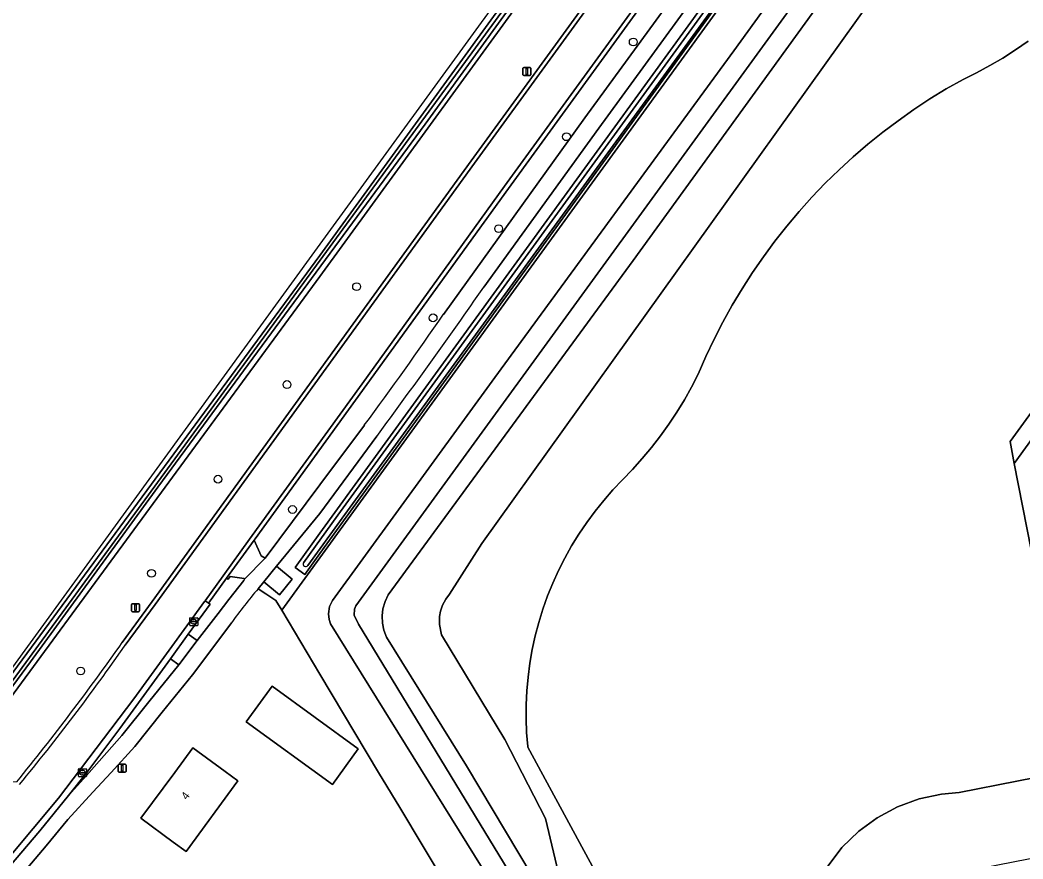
# Model space of a CAD drawing. Extents: x 152881 to 155736, y 382924 to 386919.
# Drawn here: x 152962.5 to 153087.9, y 384989.2 to 385094 of the extents above; entities that cross this region are included whole.
import ezdxf

# ---------------------------------------------------------------- set-up
doc = ezdxf.new("R2010")
doc.units = 0
for name, color, linetype in [('IMGEO_Berm_groen', 7, 'Continuous'), ('IMGEO_Boom', 7, 'Continuous'), ('IMGEO_Erf', 7, 'Continuous'), ('IMGEO_Fietspad_gesloten', 7, 'Continuous'), ('IMGEO_Groenvoorziening', 7, 'Continuous'), ('IMGEO_Kolk', 7, 'Continuous'), ('IMGEO_Lichtmast', 7, 'Continuous'), ('IMGEO_Loofbos', 7, 'Continuous'), ('IMGEO_Oever', 7, 'Continuous'), ('IMGEO_Pand', 7, 'Continuous'), ('IMGEO_Pand_nummerreeks', 7, 'Continuous'), ('IMGEO_Rijbaan_lokaal_gesloten', 7, 'Continuous'), ('IMGEO_Rijbaan_lokaal_open', 7, 'Continuous'), ('IMGEO_Verkeersbordpaal', 7, 'Continuous'), ('IMGEO_Waterloop', 7, 'Continuous')]:
    doc.layers.add(name, color=color, linetype=linetype)

msp = doc.modelspace()

# ---------------------------------------------------------------- linework, layer by layer
at = {"layer": 'IMGEO_Berm_groen'}
for points in [[(153073.4, 385137.04), (153085.12, 385153.13), (153082.24, 385153.77), (153023.56, 385073.01), (153005.89, 385048.49), (152991.9, 385029.19), (152991.77, 385029.01), (152992.68, 385027.08), (152993.15, 385026.8), (153000, 385035.96), (153005.56, 385043.4)], [(153015.45, 385057.26), (153033.13, 385081.82), (153073.4, 385137.04)]]:
    msp.add_lwpolyline(points, dxfattribs=at)
for points in [[(152988.61, 385021.62), (152990.48, 385023.99), (152990.6, 385024.15), (152990.52, 385024.24), (152988.78, 385024.48), (152988.54, 385024.15), (152988.34, 385024.29), (152986.07, 385021.17), (152986.27, 385021.02), (152983.55, 385017.27), (152984.67, 385016.47), (152987.3, 385019.88)], [(152982.36, 385013.46), (152981.33, 385014.2), (152975.01, 385005.47), (152970.89, 385000), (152968.6, 384997.09), (152971.18, 385000), (152975.26, 385004.6), (152978.61, 385008.8)]]:
    msp.add_lwpolyline(points, close=True, dxfattribs=at)
msp.add_arc((152623.6, 385326.44), 475.4, 323.4603, 325.5136, dxfattribs=at)
at = {"layer": 'IMGEO_Boom'}
for centre in [(153039.17, 385091.31), (153030.82, 385079.46), (153022.35, 385067.97), (153004.59, 385060.72), (153014.15, 385056.82), (152995.89, 385048.48), (152987.27, 385036.65), (152996.58, 385032.87), (152978.95, 385024.88), (152970.11, 385012.68)]:
    msp.add_circle(centre, 0.489, dxfattribs=at)
at = {"layer": 'IMGEO_Erf'}
for points in [[(153009.98, 384995.61), (153007.35, 385000), (153000, 385012.28), (152995.23, 385020.26), (152995.25, 385020.29), (152994.51, 385021.5), (152993.25, 385022.33), (152992.29, 385022.96)], [(152988.96, 385018.7), (152986.37, 385015.25), (152984.09, 385012.21), (152980.28, 385007.53), (152976.88, 385003.22), (152973.91, 385000), (152971.61, 384997.51), (152968.5, 384994.1), (152965.8, 384990.83), (152962.58, 384987.03)], [(153037.11, 384950.27), (153009.98, 384995.61)]]:
    msp.add_lwpolyline(points, dxfattribs=at)
for points in [[(152990.81, 385006.33), (152994.03, 385010.76), (153004.8, 385002.94), (153001.58, 384998.5)], [(152977.64, 384994.26), (152981.87, 385000), (152984.14, 385003.07), (152988.16, 385000.1), (152989.76, 384998.93), (152983.27, 384990.1), (152981.66, 384991.29)]]:
    msp.add_lwpolyline(points, close=True, dxfattribs=at)
msp.add_arc((153032.46, 384988.09), 53.19, 139.0459, 144.8753, dxfattribs=at)
at = {"layer": 'IMGEO_Fietspad_gesloten'}
for points in [[(153020.5, 385060.66), (153034.86, 385080.54), (153075.16, 385135.82), (153086.86, 385151.87), (153088.71, 385154.45), (153096.42, 385165.12), (153155.57, 385246.33), (153158.23, 385250), (153197.22, 385303.84), (153198.61, 385306.61), (153200.7, 385310.11), (153201.21, 385310.92), (153201.8, 385311.84), (153204.8, 385316.21), (153206.99, 385318.53)], [(153153.91, 385247.68), (153111.75, 385189.75), (153110.83, 385188.49), (153094.69, 385166.3), (153086.99, 385155.68), (153085.12, 385153.13), (153073.4, 385137.04), (153033.13, 385081.82), (153015.45, 385057.26)], [(153005.56, 385043.4), (153000, 385035.96), (152993.15, 385026.8), (152990.6, 385024.15), (152990.48, 385023.99), (152988.61, 385021.62), (152987.3, 385019.88), (152984.67, 385016.47), (152982.36, 385013.46), (152978.61, 385008.8), (152975.26, 385004.6), (152971.18, 385000), (152968.6, 384997.09), (152964.98, 384992.7), (152961.21, 384988.25)], [(152992.29, 385022.96), (152992.99, 385023.81), (152994.59, 385025.76), (153000, 385032.37), (153007.12, 385042.01)], [(152965.8, 384990.83), (152968.5, 384994.1), (152971.61, 384997.51), (152973.91, 385000), (152976.88, 385003.22), (152980.28, 385007.53), (152984.09, 385012.21), (152986.37, 385015.25), (152988.96, 385018.7)], [(152962.58, 384987.03), (152965.8, 384990.83)]]:
    msp.add_lwpolyline(points, dxfattribs=at)
for centre, radius, start, end in [((152288.91, 385571.47), 892.27, 323.60229, 325.0763), ((152623.6, 385326.44), 475.4, 323.4603, 325.5136), ((153032.46, 384988.09), 53.19, 139.0459, 144.8753)]:
    msp.add_arc(centre, radius, start, end, dxfattribs=at)
at = {"layer": 'IMGEO_Groenvoorziening'}
for points in [[(153162.04, 385250), (153199.79, 385301.98), (153198.73, 385302.74), (153197.22, 385303.84), (153158.23, 385250), (153155.57, 385246.33), (153096.42, 385165.12), (153088.71, 385154.45), (153090.14, 385153.44), (153088.3, 385150.85), (153086.86, 385151.87), (153075.16, 385135.82), (153034.86, 385080.54), (153020.5, 385060.66)], [(153007.12, 385042.01), (153000, 385032.37), (152994.59, 385025.76), (152996.55, 385024.15), (152994.96, 385022.2), (152992.99, 385023.81), (152992.29, 385022.96), (152993.25, 385022.33), (152994.51, 385021.5), (152995.25, 385020.29), (153162.04, 385250)], [(153162.04, 385250), (152995.25, 385020.29), (152995.23, 385020.26), (153000, 385012.28), (153007.35, 385000), (153009.98, 384995.61), (153037.11, 384950.27)], [(153164.79, 385228.23), (153133.84, 385185.19), (153103.74, 385143.75), (153071.3, 385099.91), (153020.24, 385028.62), (153016.19, 385022.27), (153015.73, 385021.65), (153015.34, 385020.91), (153015.09, 385020.17), (153014.96, 385019.47), (153014.94, 385018.47), (153015.21, 385017.19), (153023.11, 385004.09), (153028.21, 384994.23), (153029.99, 384986.7)], [(153218.46, 385220.12), (153195.63, 385188.65), (153170.9, 385154.56), (153144.44, 385118.1), (153119.93, 385084.35), (153098.77, 385055.18), (153086.8, 385038.63), (153094.33, 385000.3), (153096.23, 384990.65), (153073.02, 384986.11)], [(153028.71, 384974.52), (153001.35, 385018.59), (153001.17, 385019.1), (153001.07, 385019.8), (153001.2, 385020.72), (153001.57, 385021.49), (153021.87, 385049.38), (153051.75, 385090.2), (153143.44, 385216.88)], [(153094.35, 385195.81), (153085.56, 385183.72), (153076.06, 385170.64), (153077.51, 385169.6), (153076.65, 385168.36), (153075.17, 385169.42), (153058.94, 385147.09), (153000, 385066.03)], [(152975.29, 385016.24), (152979.03, 385021.37), (153018.92, 385076.46), (153077.76, 385157.41), (153076.54, 385160.34), (153071.56, 385163.75), (153073.52, 385166.38), (153078.5, 385162.91), (153081.57, 385162.66), (153094.38, 385180.27)], [(153169.09, 385155.23), (153086.26, 385041.38), (153086.8, 385038.63), (153098.77, 385055.18)], [(153094.33, 385000.3), (153079.92, 384997.47), (153077.69, 384997.29), (153074.89, 384996.68), (153072.2, 384995.68), (153069.67, 384994.33), (153067.35, 384992.64), (153065.25, 384990.62), (153046.46, 384965.39), (153025.99, 385003.14), (153025.98, 385003.23), (153025.84, 385004.97), (153025.77, 385006.71), (153025.78, 385008.45), (153025.87, 385010.18), (153026.02, 385011.92), (153026.25, 385013.65), (153026.55, 385015.36), (153026.92, 385017.06), (153027.36, 385018.74), (153027.88, 385020.41), (153028.46, 385022.05), (153029.11, 385023.66), (153029.83, 385025.25), (153030.62, 385026.8), (153031.47, 385028.32), (153032.38, 385029.8), (153033.36, 385031.25), (153034.39, 385032.65), (153035.49, 385034), (153036.63, 385035.31), (153037.84, 385036.57), (153039.09, 385037.88), (153040.3, 385039.23), (153041.46, 385040.62), (153042.57, 385042.06), (153043.62, 385043.53), (153044.62, 385045.04), (153045.57, 385046.59), (153046.45, 385048.17), (153047.28, 385049.78), (153048.24, 385051.99), (153049.27, 385054.16), (153050.37, 385056.3), (153051.54, 385058.4), (153052.77, 385060.46), (153054.07, 385062.48), (153055.43, 385064.46), (153056.86, 385066.4), (153058.35, 385068.29), (153059.9, 385070.12), (153061.5, 385071.91), (153063.17, 385073.65), (153064.89, 385075.33), (153066.66, 385076.95), (153068.48, 385078.52), (153070.35, 385080.03), (153072.27, 385081.47), (153074.24, 385082.86), (153076.25, 385084.18), (153078.3, 385085.43), (153080.39, 385086.62), (153082.08, 385087.45), (153083.74, 385088.35), (153085.37, 385089.3), (153086.96, 385090.32), (153088.51, 385091.4)], [(153000, 385066.03), (152987.38, 385048.67), (152957, 385006.89), (152951.3, 385000), (152949.25, 384997.53), (152949.06, 384997.32), (152948.98, 384997.23), (152949.2, 384997.13), (152949.77, 384996.78), (152956.01, 384992.15), (152956.27, 384991.93), (152958.08, 384994.05), (152957.16, 384996.76), (152953.13, 385000), (152952.82, 385000.25), (152952.4, 385000.59), (152954.33, 385002.81), (152954.72, 385002.49), (152957.78, 385000), (152959, 384999), (152962.1, 384998.82)]]:
    msp.add_lwpolyline(points, dxfattribs=at)
for points in [[(153000, 385062), (152957.36, 385003.99), (152956.59, 385004.68), (152956.14, 385005.09), (153000, 385064.61), (153059.58, 385146.65), (153070.73, 385162), (153072.14, 385161.17), (153060.9, 385145.72)], [(153076.27, 385135.05), (153086.45, 385149.09), (153087.17, 385148.56), (153087.55, 385148.28), (153077.4, 385134.26), (153000, 385027.35), (152998.11, 385024.74), (152996.9, 385025.62), (153000, 385029.9)]]:
    msp.add_lwpolyline(points, close=True, dxfattribs=at)
for centre, radius, start, end in [((152288.91, 385571.47), 892.27, 323.60229, 325.0763), ((152724.12, 385192.62), 306.92, 320.841, 324.9209)]:
    msp.add_arc(centre, radius, start, end, dxfattribs=at)
at = {"layer": 'IMGEO_Kolk'}
for p, q in [((152983.73, 385018.42), (152983.73, 385019.27)), ((152983.81, 385019.34), (152984.66, 385019.34)), ((152984.73, 385019.27), (152984.73, 385018.42)), ((152984.66, 385018.34), (152983.81, 385018.34)), ((152983.99, 385018.84), (152983.99, 385018.85)), ((152984.03, 385018.89), (152984.43, 385018.89)), ((152984.43, 385018.8), (152984.03, 385018.8)), ((152984.22, 385019.12), (152984.25, 385019.12)), ((152984.24, 385018.56), (152984.22, 385018.56)), ((152984.48, 385018.85), (152984.48, 385018.84)), ((152969.9, 385000.46), (152970.75, 385000.46)), ((152969.82, 384999.53), (152969.82, 385000.39)), ((152970.75, 384999.46), (152969.9, 384999.46)), ((152970.08, 384999.95), (152970.08, 384999.97)), ((152970.52, 384999.92), (152970.12, 384999.92)), ((152970.13, 385000), (152970.52, 385000)), ((152970.31, 385000.24), (152970.34, 385000.24)), ((152970.33, 384999.68), (152970.31, 384999.68)), ((152970.57, 384999.97), (152970.57, 384999.95)), ((152970.83, 385000.39), (152970.83, 384999.53))]:
    msp.add_line(p, q, dxfattribs=at)
for points in [[(152983.73, 385018.42), (152983.73, 385019.27)], [(152983.81, 385019.34), (152984.66, 385019.34)], [(152984.73, 385019.27), (152984.73, 385018.42)], [(152984.66, 385018.34), (152983.81, 385018.34)], [(152969.9, 385000.46), (152970.75, 385000.46)], [(152969.82, 384999.53), (152969.82, 385000.39)], [(152970.75, 384999.46), (152969.9, 384999.46)], [(152970.83, 385000.39), (152970.83, 384999.53)]]:
    msp.add_lwpolyline(points, dxfattribs=at)
for centre, radius, start, end in [((152983.81, 385019.27), 0.0765, 91.552, 178.448), ((152983.81, 385019.27), 0.0765, 91.552, 178.448), ((152984.66, 385019.27), 0.0765, 1.552, 88.448), ((152984.66, 385019.27), 0.0765, 1.552, 88.448), ((152983.81, 385018.42), 0.0765, 181.552, 268.448), ((152983.81, 385018.42), 0.0765, 181.552, 268.448), ((152984.03, 385018.85), 0.0403, 85.8775, 175.7526), ((152984.03, 385018.84), 0.0366, 178.938, 274.7102), ((152984.44, 385018.85), 0.0386, 1.7309, 96.639), ((152984.43, 385018.84), 0.043, 264.8664, 352.4533), ((152984.66, 385018.42), 0.0765, 271.552, 358.448), ((152984.66, 385018.42), 0.0765, 271.552, 358.448), ((152969.9, 385000.39), 0.0765, 91.552, 178.448), ((152969.9, 385000.39), 0.0765, 91.552, 178.448), ((152970.75, 385000.39), 0.0765, 1.552, 88.448), ((152970.75, 385000.39), 0.0765, 1.552, 88.448), ((152969.9, 384999.54), 0.0765, 181.552, 268.448), ((152969.9, 384999.54), 0.0765, 181.552, 268.448), ((152970.12, 384999.96), 0.0403, 85.8775, 175.7526), ((152970.12, 384999.95), 0.0366, 178.938, 274.7102), ((152970.53, 384999.97), 0.0386, 1.7309, 96.639), ((152970.52, 384999.96), 0.043, 264.8664, 352.4533), ((152970.75, 384999.54), 0.0765, 271.552, 358.448), ((152970.75, 384999.54), 0.0765, 271.552, 358.448)]:
    msp.add_arc(centre, radius, start, end, dxfattribs=at)
for centre, major_axis, ratio, start_param, end_param in [((152984.22, 385018.84), (-0.387, 0.002), 0.722429, 4.712389, 7.853982), ((152984.24, 385018.84), (-0.39, 0.002), 0.717154, 1.570796, 4.712389), ((152970.31, 384999.96), (-0.387, 0.002), 0.722429, 4.712389, 7.853982), ((152970.34, 384999.96), (-0.39, 0.002), 0.717154, 1.570796, 4.712389)]:
    msp.add_ellipse(centre, major_axis=major_axis, ratio=ratio, start_param=start_param, end_param=end_param, dxfattribs=at)
at = {"layer": 'IMGEO_Lichtmast'}
for p, q in [((153025.38, 385087.22), (153025.38, 385088.02)), ((153025.38, 385088.02), (153025.38, 385087.22)), ((153025.48, 385088.12), (153026.27, 385088.12)), ((153026.27, 385088.12), (153025.48, 385088.12)), ((153026.27, 385087.12), (153025.48, 385087.12)), ((153025.48, 385087.12), (153026.27, 385087.12)), ((153026.37, 385088.02), (153026.37, 385087.22)), ((153026.37, 385087.22), (153026.37, 385088.02)), ((152974.79, 385000.12), (152974.79, 385000.92)), ((152974.79, 385000.92), (152974.79, 385000.12)), ((152974.89, 385001.02), (152975.68, 385001.02)), ((152975.68, 385001.02), (152974.89, 385001.02)), ((152975.78, 385000.92), (152975.78, 385000.12)), ((152975.78, 385000.12), (152975.78, 385000.92)), ((152975.68, 385000.02), (152974.89, 385000.02)), ((152974.89, 385000.02), (152975.68, 385000.02))]:
    msp.add_line(p, q, dxfattribs=at)
for points in [[(153025.8, 385087.99), (153025.95, 385087.99), (153025.95, 385087.24), (153025.8, 385087.24), (153025.8, 385087.99)], [(152975.21, 385000.9), (152975.36, 385000.9), (152975.36, 385000.15), (152975.21, 385000.15), (152975.21, 385000.9)]]:
    msp.add_lwpolyline(points, dxfattribs=at)
for centre, start, end in [((153025.48, 385088.02), 90, 180), ((153025.48, 385088.02), 90, 180), ((153025.48, 385087.22), 180, 270), ((153025.48, 385087.22), 180, 270), ((153026.27, 385088.02), 0, 90), ((153026.27, 385088.02), 360, 90), ((153026.27, 385087.22), 270, 0), ((153026.27, 385087.22), 270, 0), ((152974.89, 385000.92), 90, 180), ((152974.89, 385000.92), 90, 180), ((152975.68, 385000.92), 0, 90), ((152975.68, 385000.92), 360, 90), ((152974.89, 385000.12), 180, 270), ((152974.89, 385000.12), 180, 270), ((152975.68, 385000.12), 270, 0), ((152975.68, 385000.12), 270, 0)]:
    msp.add_arc(centre, 0.1, start, end, dxfattribs=at)
at = {"layer": 'IMGEO_Loofbos'}
msp.add_lwpolyline([(153088.51, 385091.4), (153086.96, 385090.32), (153085.37, 385089.3), (153083.74, 385088.35), (153082.08, 385087.45), (153080.39, 385086.62), (153078.3, 385085.43), (153076.25, 385084.18), (153074.24, 385082.86), (153072.27, 385081.47), (153070.35, 385080.03), (153068.48, 385078.52), (153066.66, 385076.95), (153064.89, 385075.33), (153063.17, 385073.65), (153061.5, 385071.91), (153059.9, 385070.12), (153058.35, 385068.29), (153056.86, 385066.4), (153055.43, 385064.46), (153054.07, 385062.48), (153052.77, 385060.46), (153051.54, 385058.4), (153050.37, 385056.3), (153049.27, 385054.16), (153048.24, 385051.99), (153047.28, 385049.78), (153046.45, 385048.17), (153045.57, 385046.59), (153044.62, 385045.04), (153043.62, 385043.53), (153042.57, 385042.06), (153041.46, 385040.62), (153040.3, 385039.23), (153039.09, 385037.88), (153037.84, 385036.57), (153036.63, 385035.31), (153035.49, 385034), (153034.39, 385032.65), (153033.36, 385031.25), (153032.38, 385029.8), (153031.47, 385028.32), (153030.62, 385026.8), (153029.83, 385025.25), (153029.11, 385023.66), (153028.46, 385022.05), (153027.88, 385020.41), (153027.36, 385018.74), (153026.92, 385017.06), (153026.55, 385015.36), (153026.25, 385013.65), (153026.02, 385011.92), (153025.87, 385010.18), (153025.78, 385008.45), (153025.77, 385006.71), (153025.84, 385004.97), (153025.98, 385003.23), (153025.99, 385003.14), (153046.46, 384965.39), (153065.25, 384990.62), (153067.35, 384992.64), (153069.67, 384994.33), (153072.2, 384995.68), (153074.89, 384996.68), (153077.69, 384997.29), (153079.92, 384997.47), (153094.33, 385000.3), (153086.8, 385038.63), (153086.26, 385041.38), (153169.09, 385155.23)], dxfattribs=at)
at = {"layer": 'IMGEO_Oever'}
for points in [[(153159.92, 385231.51), (153129.3, 385188.47), (153039.17, 385063.98), (153008.54, 385022.2), (153008.15, 385021.36), (153007.89, 385020.43), (153007.79, 385019.57), (153007.82, 385018.67), (153008, 385017.79), (153008.32, 385016.91), (153018.32, 385000.81), (153029.76, 384981.69)], [(153029.99, 384986.7), (153028.21, 384994.23), (153023.11, 385004.09), (153015.21, 385017.19), (153014.94, 385018.47), (153014.96, 385019.47), (153015.09, 385020.17), (153015.34, 385020.91), (153015.73, 385021.65), (153016.19, 385022.27), (153020.24, 385028.62), (153071.3, 385099.91), (153103.74, 385143.75), (153133.84, 385185.19), (153164.79, 385228.23)], [(153143.44, 385216.88), (153051.75, 385090.2), (153021.87, 385049.38), (153001.57, 385021.49), (153001.2, 385020.72), (153001.07, 385019.8), (153001.17, 385019.1), (153001.35, 385018.59), (153028.71, 384974.52), (153030.48, 384974.12), (153031.24, 384974.54), (153027.85, 384980.66), (153004.85, 385018.52), (153004.27, 385019.65), (153004.32, 385020.4), (153004.5, 385020.82), (153097.68, 385149.01), (153147.74, 385218.13)], [(152957.41, 385005.8), (153053.3, 385136.85), (153056.74, 385141.43), (153070.94, 385161.14)], [(153071.16, 385160.99), (153059.38, 385144.59), (153038.8, 385116.36), (153013.17, 385081.03), (152979.75, 385035.65), (152963.84, 385013.81), (152957.77, 385005.61)], [(152997.94, 385026.2), (153002.25, 385032.14), (153047.82, 385094.81), (153074.19, 385130.99), (153074.53, 385131.47), (153086.34, 385148.14)], [(153086.87, 385147.77), (153078.32, 385135.99), (153074.58, 385130.71), (153048.34, 385094.43), (153002.77, 385031.76), (152998.5, 385025.88)]]:
    msp.add_lwpolyline(points, dxfattribs=at)
for points in [[(153072.14, 385161.17), (153070.73, 385162), (153059.58, 385146.65), (153000, 385064.61), (152956.14, 385005.09), (152956.59, 385004.68), (152957.36, 385003.99), (153000, 385062), (153060.9, 385145.72)], [(153087.17, 385148.56), (153086.45, 385149.09), (153076.27, 385135.05), (153000, 385029.9), (152996.9, 385025.62), (152998.11, 385024.74), (153000, 385027.35), (153077.4, 385134.26), (153087.55, 385148.28)]]:
    msp.add_lwpolyline(points, close=True, dxfattribs=at)
msp.add_arc((152998.23, 385026.05), 0.322, 151.4522, 328.4188, dxfattribs=at)
at = {"layer": 'IMGEO_Pand'}
for points in [[(152994.03, 385010.76), (152990.81, 385006.33), (153001.58, 384998.5), (153004.8, 385002.94)], [(152988.16, 385000.1), (152984.14, 385003.07), (152981.87, 385000), (152977.64, 384994.26), (152981.66, 384991.29), (152983.27, 384990.1), (152989.76, 384998.93)]]:
    msp.add_lwpolyline(points, close=True, dxfattribs=at)
at = {"layer": 'IMGEO_Rijbaan_lokaal_gesloten'}
for points in [[(153203.23, 385321.19), (153070.76, 385138.88), (153023.09, 385073.28), (153005.3, 385048.58), (152991.21, 385029.16), (152987.93, 385024.58), (152985.66, 385021.46), (152986.05, 385021.18), (152986.07, 385021.17), (152988.34, 385024.29), (152991.77, 385029.01), (152991.9, 385029.19), (153005.89, 385048.49), (153023.56, 385073.01), (153082.24, 385153.77), (153085.57, 385158.35), (153108.63, 385190.09), (153109.55, 385191.35), (153192.43, 385305.43), (153196.07, 385310.44), (153200.94, 385317.14), (153204.35, 385321.82)], [(153066.93, 385141.65), (153077.99, 385156.86), (153077.76, 385157.41), (153018.92, 385076.46), (152979.03, 385021.37), (152975.29, 385016.24)], [(153023.09, 385073.28), (153070.76, 385138.88), (153066.93, 385141.65), (153019.31, 385076.15), (152979.41, 385021), (152975.68, 385015.91)], [(152975.68, 385015.91), (152979.41, 385021), (153019.31, 385076.15), (153066.93, 385141.65)], [(152934.41, 384970.71), (152920.09, 384959.42), (152918.37, 384958.27), (152921.58, 384953.96), (152931.36, 384961.41), (152937.22, 384966.04), (152946.43, 384974.27), (152949.59, 384977.42), (152957.23, 384984.97), (152960.99, 384989.19), (152967.34, 384996.77), (152976.73, 385009.19), (152985.59, 385021.36), (152985.66, 385021.46), (152987.93, 385024.58), (152991.21, 385029.16), (153005.3, 385048.58), (153023.09, 385073.28)]]:
    msp.add_lwpolyline(points, dxfattribs=at)
for centre, radius, start, end in [((152724.12, 385192.62), 306.92, 320.841, 324.9209), ((152756.38, 385168.52), 267.17, 320.4781, 325.1641), ((152756.38, 385168.52), 267.17, 320.4781, 325.1641)]:
    msp.add_arc(centre, radius, start, end, dxfattribs=at)
at = {"layer": 'IMGEO_Rijbaan_lokaal_open'}
for points in [[(152993.15, 385026.8), (152992.68, 385027.08), (152991.77, 385029.01), (152988.34, 385024.29), (152988.54, 385024.15), (152988.78, 385024.48), (152990.52, 385024.24), (152990.6, 385024.15)], [(152996.55, 385024.15), (152994.59, 385025.76), (152992.99, 385023.81), (152994.96, 385022.2)], [(152984.67, 385016.47), (152983.55, 385017.27), (152981.33, 385014.2), (152982.36, 385013.46)]]:
    msp.add_lwpolyline(points, close=True, dxfattribs=at)
msp.add_lwpolyline([(152961.21, 384988.25), (152964.98, 384992.7), (152968.6, 384997.09), (152970.89, 385000), (152975.01, 385005.47), (152981.33, 385014.2), (152983.55, 385017.27), (152986.27, 385021.02), (152986.07, 385021.17), (152986.05, 385021.18), (152985.66, 385021.46), (152985.59, 385021.36), (152976.73, 385009.19), (152967.34, 384996.77), (152960.99, 384989.19), (152957.23, 384984.97), (152949.59, 384977.42), (152946.43, 384974.27), (152937.22, 384966.04), (152931.36, 384961.41), (152921.58, 384953.96), (152917.33, 384950.61)], dxfattribs=at)
at = {"layer": 'IMGEO_Verkeersbordpaal'}
for p, q in [((152976.47, 385020.19), (152976.47, 385020.99)), ((152976.47, 385020.99), (152976.47, 385020.19)), ((152976.57, 385021.09), (152977.35, 385021.09)), ((152977.35, 385021.09), (152976.57, 385021.09)), ((152977.45, 385020.99), (152977.45, 385020.19)), ((152977.45, 385020.19), (152977.45, 385020.99)), ((152977.35, 385020.09), (152976.57, 385020.09)), ((152976.57, 385020.09), (152977.35, 385020.09))]:
    msp.add_line(p, q, dxfattribs=at)
msp.add_lwpolyline([(152976.88, 385020.97), (152977.04, 385020.97), (152977.04, 385020.22), (152976.88, 385020.22), (152976.88, 385020.97)], dxfattribs=at)
for centre, start, end in [((152976.57, 385020.99), 90, 180), ((152976.57, 385020.99), 90, 180), ((152977.35, 385020.99), 0, 90), ((152977.35, 385020.99), 360, 90), ((152976.57, 385020.19), 180, 270), ((152976.57, 385020.19), 180, 270), ((152977.35, 385020.19), 270, 0), ((152977.35, 385020.19), 270, 0)]:
    msp.add_arc(centre, 0.1, start, end, dxfattribs=at)
at = {"layer": 'IMGEO_Waterloop'}
for points in [[(153147.74, 385218.13), (153097.68, 385149.01), (153004.5, 385020.82), (153004.32, 385020.4), (153004.27, 385019.65), (153004.85, 385018.52), (153027.85, 384980.66), (153031.24, 384974.54), (153033.16, 384975.6), (153029.76, 384981.69), (153018.32, 385000.81), (153008.32, 385016.91), (153008, 385017.79), (153007.82, 385018.67), (153007.79, 385019.57), (153007.89, 385020.43), (153008.15, 385021.36), (153008.54, 385022.2), (153039.17, 385063.98), (153129.3, 385188.47), (153159.92, 385231.51)], [(153070.94, 385161.14), (153056.74, 385141.43), (153053.3, 385136.85), (152957.41, 385005.8)], [(152957.77, 385005.61), (152963.84, 385013.81), (152979.75, 385035.65), (153013.17, 385081.03), (153038.8, 385116.36), (153059.38, 385144.59), (153071.16, 385160.99)], [(153086.34, 385148.14), (153074.53, 385131.47), (153074.19, 385130.99), (153047.82, 385094.81), (153002.25, 385032.14), (152997.94, 385026.2)], [(152998.5, 385025.88), (153002.77, 385031.76), (153048.34, 385094.43), (153074.58, 385130.71), (153078.32, 385135.99), (153086.87, 385147.77)]]:
    msp.add_lwpolyline(points, dxfattribs=at)
msp.add_arc((152998.23, 385026.05), 0.322, 151.4522, 328.4188, dxfattribs=at)

# ---------------------------------------------------------------- texts
at = {"layer": 'IMGEO_Pand_nummerreeks'}
msp.add_text('4', height=1, rotation=53.5864, dxfattribs=at).set_placement((152983.37, 384996.5))

doc.saveas('drawing.dxf')
